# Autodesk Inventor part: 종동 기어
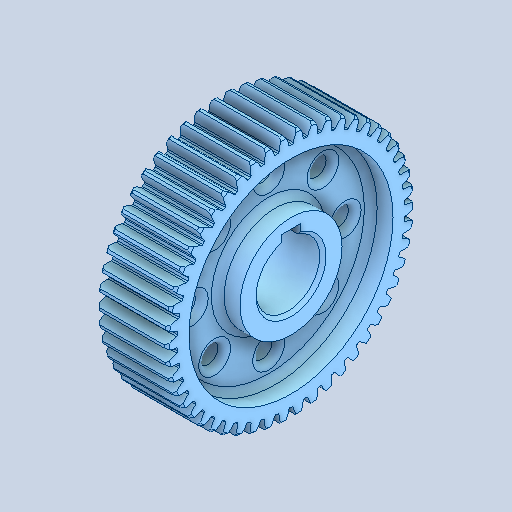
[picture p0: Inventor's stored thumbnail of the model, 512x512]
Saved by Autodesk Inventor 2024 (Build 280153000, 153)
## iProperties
Created: 2025-11
Part Number: 종동 기어
Material: 강철, 탄소
Document SubType Name: Modeling
Designer: Edu07
Density: 7.85 g/cm^3
Appearance: 기본값
Author: jhkim
Sending System: Autodesk Inventor 2026
Preprocessor: ST-DEVELOPER v20.1
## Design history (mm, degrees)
node "종동 기어1"
node "솔리드2"
node "솔리드1"
